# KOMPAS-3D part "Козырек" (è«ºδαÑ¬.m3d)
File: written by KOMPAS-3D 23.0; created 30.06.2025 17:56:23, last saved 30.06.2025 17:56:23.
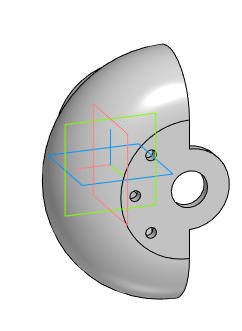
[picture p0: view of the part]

Document properties: Автор: Inspektor_Kot; Полное имя файла: I:\Autodesk Inventor Projects\2025 Варианты\Демовариант\Козырек.m3d

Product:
- Part/product: Козырек

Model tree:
1. Операция без истории:1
